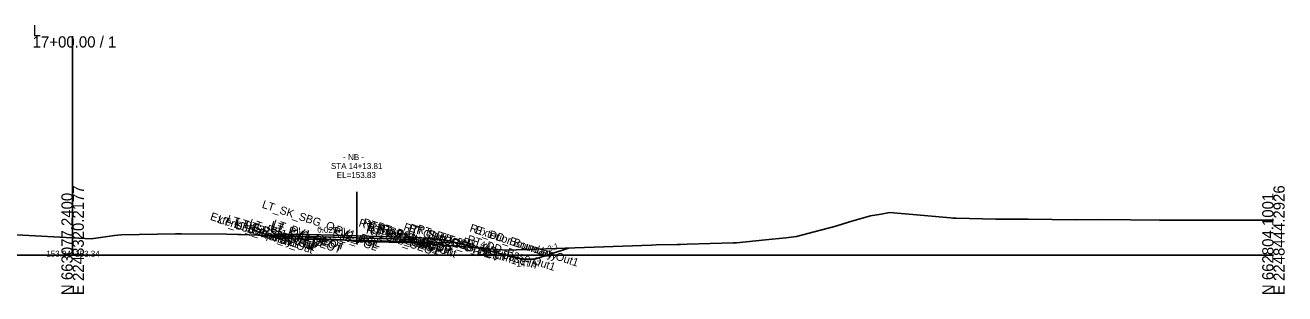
# Model space of a CAD drawing. Extents: x -26 to 2603, y -10 to 9566.
# Drawn here: x 288.1 to 602.8, y 6990.3 to 7057.6 of the extents above; entities that cross this region are included whole.
import ezdxf

# ---------------------------------------------------------------- set-up
doc = ezdxf.new("R2010")
doc.units = 0
for name, color, linetype in [('Exist Cross Section Cell', 7, 'Continuous'), ('Exist XS Center Line Elevation Label', 7, 'Continuous'), ('Exist XS Ground Line', 7, 'Continuous'), ('Prop CMT Ditch DDE', 7, 'Continuous'), ('Prop CMT Pvmt Course 1', 7, 'Continuous'), ('Prop CMT Pvmt Course 2', 7, 'Continuous'), ('Prop CMT Pvmt Surface', 7, 'Continuous'), ('Prop CMT Pvmt Surface Overlay', 7, 'Continuous'), ('Prop CMT Pvmt Surface Shoulder', 7, 'Continuous'), ('Prop CMT Shld Paved Course 1', 7, 'Continuous'), ('Prop CMT Shld Paved Course 2', 7, 'Continuous'), ('Prop CMT Slope Grass', 7, 'Continuous'), ('Prop CMT Subgrade Earthwork', 7, 'Continuous'), ('Prop XS Ditch Standard Text', 7, 'Continuous'), ('Prop XS SE Text', 7, 'Continuous'), ('Prop XS Side Slope Text', 7, 'Continuous'), ('Prop XS Vertical Lines Alignments', 7, 'Continuous'), ('Scratch_Level_1', 7, 'Continuous'), ('Scratch_Level_9', 7, 'Continuous')]:
    doc.layers.add(name, color=color, linetype=linetype)

msp = doc.modelspace()

# ---------------------------------------------------------------- linework, layer by layer
at = {"layer": 'Exist Cross Section Cell'}
for p, q in [((300, 7000), (300, 7054.78)), ((0, 7000), (300, 7000)), ((300, 7000), (600, 7000))]:
    msp.add_line(p, q, dxfattribs=at)
at = {"layer": 'Exist XS Ground Line'}
for p, q in [((490.67, 7007.28), (494.09, 7008.33)), ((494.09, 7008.33), (499.31, 7009.83)), ((499.31, 7009.83), (502.01, 7010.23)), ((502.01, 7010.23), (504.04, 7010.69)), ((504.04, 7010.69), (509.94, 7010.17)), ((509.94, 7010.17), (519.31, 7009.36)), ((519.31, 7009.36), (519.89, 7009.29)), ((519.89, 7009.29), (520.77, 7009.26)), ((520.77, 7009.26), (530.66, 7009.02)), ((530.66, 7009.02), (538.75, 7009)), ((538.75, 7009), (550.71, 7008.88)), ((550.71, 7008.88), (557.04, 7008.89)), ((557.04, 7008.89), (571.52, 7008.79)), ((571.52, 7008.79), (575.13, 7008.77)), ((575.13, 7008.77), (591.35, 7008.77)), ((591.35, 7008.77), (600, 7008.72)), ((286.01, 7005.1), (300, 7004.34)), ((310.44, 7004.88), (312.11, 7005.1)), ((312.11, 7005.1), (325.71, 7005.32)), ((325.71, 7005.32), (326.36, 7005.33)), ((326.36, 7005.33), (327.24, 7005.32)), ((327.24, 7005.32), (338.51, 7005.25)), ((338.51, 7005.25), (341.25, 7005.18)), ((341.25, 7005.18), (342.02, 7005.16)), ((342.02, 7005.16), (350.42, 7004.85)), ((480.87, 7004.63), (485.28, 7005.81)), ((485.28, 7005.81), (490.67, 7007.28)), ((300, 7004.34), (304.62, 7004.09)), ((304.62, 7004.09), (310.44, 7004.88)), ((350.42, 7004.85), (354.74, 7004.67)), ((354.74, 7004.67), (355.7, 7004.63)), ((355.7, 7004.63), (358.11, 7004.55)), ((358.11, 7004.55), (360.74, 7004.27)), ((360.74, 7004.27), (362.9, 7004)), ((362.9, 7004), (365.87, 7003.95)), ((365.87, 7003.95), (368.24, 7003.77)), ((368.24, 7003.77), (370.14, 7003.49)), ((370.14, 7003.49), (372.25, 7003.42)), ((372.25, 7003.42), (382.45, 7003.15)), ((382.45, 7003.15), (387.22, 7003.04)), ((387.22, 7003.04), (388.6, 7002.94)), ((388.6, 7002.94), (392.59, 7002.51)), ((392.59, 7002.51), (404.15, 7001.59)), ((418.2, 7001.59), (430.3, 7001.98)), ((430.3, 7001.98), (444.59, 7002.51)), ((444.59, 7002.51), (445.76, 7002.56)), ((445.76, 7002.56), (451.02, 7002.63)), ((451.02, 7002.63), (451.86, 7002.66)), ((451.86, 7002.66), (453.53, 7002.74)), ((453.53, 7002.74), (465.01, 7003.09)), ((465.01, 7003.09), (465.85, 7003.12)), ((465.85, 7003.12), (473.09, 7003.82)), ((473.09, 7003.82), (478.2, 7004.3)), ((478.2, 7004.3), (480.87, 7004.63)), ((404.15, 7001.59), (408.43, 7001.23)), ((408.43, 7001.23), (410.92, 7001.34)), ((410.92, 7001.34), (418.2, 7001.59))]:
    msp.add_line(p, q, dxfattribs=at)
at = {"layer": 'Prop CMT Ditch DDE'}
msp.add_lwpolyline([(401.01, 7001.83), (401.02, 7001.83), (412.46, 6998.97), (415.46, 6998.97), (423.85, 7001.77)], dxfattribs=at)
at = {"layer": 'Prop CMT Pvmt Course 1'}
for points in [[(370.97, 7004.83), (358.97, 7005.13)], [(358.97, 7005.13), (358.97, 7004.63)], [(358.97, 7004.63), (370.97, 7004.33)], [(370.97, 7004.33), (370.97, 7004.83)], [(370.97, 7004.83), (382.97, 7004.53)], [(370.97, 7004.33), (370.97, 7004.83)], [(382.97, 7004.03), (370.97, 7004.33)], [(382.97, 7004.53), (382.97, 7004.03)]]:
    msp.add_lwpolyline(points, dxfattribs=at)
at = {"layer": 'Prop CMT Pvmt Course 2'}
for points in [[(370.97, 7004.33), (358.97, 7004.63)], [(358.97, 7004.63), (358.97, 7003.97)], [(358.97, 7003.97), (370.97, 7003.67)], [(370.97, 7003.67), (370.97, 7004.33)], [(370.97, 7003.67), (370.97, 7004.33)], [(370.97, 7004.33), (382.97, 7004.03)], [(382.97, 7003.37), (370.97, 7003.67)], [(382.97, 7004.03), (382.97, 7003.37)]]:
    msp.add_lwpolyline(points, dxfattribs=at)
at = {"layer": 'Prop CMT Pvmt Surface'}
for points in [[(370.97, 7004.83), (358.97, 7005.13)], [(370.97, 7004.83), (382.97, 7004.53)]]:
    msp.add_lwpolyline(points, dxfattribs=at)
at = {"layer": 'Prop CMT Pvmt Surface Overlay'}
for points in [[(370.97, 7004.83), (358.97, 7005.13)], [(370.97, 7004.83), (382.97, 7004.53)]]:
    msp.add_lwpolyline(points, dxfattribs=at)
at = {"layer": 'Prop CMT Pvmt Surface Shoulder'}
for points in [[(358.97, 7005.13), (352.97, 7005.29)], [(382.97, 7004.53), (384.97, 7004.48)]]:
    msp.add_lwpolyline(points, dxfattribs=at)
at = {"layer": 'Prop CMT Shld Paved Course 1'}
for points in [[(358.97, 7005.13), (352.97, 7005.29), (352.48, 7004.8)], [(358.97, 7004.63), (358.97, 7005.13)], [(352.48, 7004.8), (358.97, 7004.63)], [(382.97, 7004.53), (384.97, 7004.48), (385.48, 7003.97)], [(382.97, 7004.03), (382.97, 7004.53)], [(385.48, 7003.97), (382.97, 7004.03)]]:
    msp.add_lwpolyline(points, dxfattribs=at)
at = {"layer": 'Prop CMT Shld Paved Course 2'}
for points in [[(358.97, 7004.63), (352.48, 7004.8), (351.98, 7004.81), (351.33, 7004.16)], [(351.33, 7004.16), (358.97, 7003.97)], [(358.97, 7003.97), (358.97, 7004.63)], [(382.97, 7004.03), (385.48, 7003.97), (385.98, 7003.96), (386.67, 7003.28)], [(382.97, 7003.37), (382.97, 7004.03)], [(386.67, 7003.28), (382.97, 7003.37)]]:
    msp.add_lwpolyline(points, dxfattribs=at)
at = {"layer": 'Prop CMT Slope Grass'}
for points in [[(350.96, 7005.21), (349.6, 7004.87)], [(352.97, 7005.29), (350.96, 7005.21)], [(384.97, 7004.48), (392.97, 7003.84)], [(392.97, 7003.84), (401.01, 7001.83)]]:
    msp.add_lwpolyline(points, dxfattribs=at)
at = {"layer": 'Prop CMT Subgrade Earthwork'}
msp.add_line((351.33, 7004.16), (349.6, 7004.87), dxfattribs=at)
for points in [[(358.97, 7003.97), (351.33, 7004.16)], [(351.33, 7004.16), (396.2, 7003.04)], [(370.97, 7003.67), (358.97, 7003.97)], [(370.97, 7003.67), (382.97, 7003.37)], [(382.97, 7003.37), (386.67, 7003.28)], [(386.67, 7003.28), (396.2, 7003.04)]]:
    msp.add_lwpolyline(points, dxfattribs=at)
at = {"layer": 'Prop XS Vertical Lines Alignments'}
msp.add_line((370.97, 7015.83), (370.97, 7002.83), dxfattribs=at)

# ---------------------------------------------------------------- texts
at = {"layer": 'Exist Cross Section Cell'}
for s, p in [('L', (290, 7054.78)), ('17+00.00 / 1', (290, 7051.98))]:
    msp.add_text(s, height=2.8, dxfattribs=at).set_placement(p)
for s, p in [('N 663077.2400', (300, 6990)), ('E 2248320.2177', (302.8, 6990)), ('N 662804.1001', (600, 6990)), ('E 2248444.2926', (602.8, 6990))]:
    msp.add_text(s, height=2.8, rotation=90, dxfattribs=at).set_placement(p)
at = {"layer": 'Exist XS Center Line Elevation Label'}
for p in [(293.42, 6999.59), (300.63, 6999.59)]:
    msp.add_text('153.34', height=1.5, dxfattribs=at).set_placement(p)
at = {"layer": 'Prop XS Ditch Standard Text'}
msp.add_text('147.97', height=1.5, dxfattribs=at).set_placement((410.88, 6997.15))
at = {"layer": 'Prop XS SE Text'}
for p in [(361.1, 7005.64), (374.3, 7005.18)]:
    msp.add_text('0.025', height=1.5, rotation=358.5434, dxfattribs=at).set_placement(p)
at = {"layer": 'Prop XS Side Slope Text'}
for s, rotation, p in [('4:1', 346.0018, (401.78, 7002.17)), ('3:1', 18.4232, (418.97, 7000.78))]:
    msp.add_text(s, height=1.5, rotation=rotation, dxfattribs=at).set_placement(p)
at = {"layer": 'Prop XS Vertical Lines Alignments'}
for s, p in [('- NB -', (367.58, 7023.81)), ('STA 14+13.81', (364.52, 7021.56))]:
    msp.add_text(s, height=1.5, dxfattribs=at).set_placement(p)
at = {"layer": 'Scratch_Level_1'}
msp.add_text('EL=153.83', height=1.5, dxfattribs=at).set_placement((366, 7019.31))
at = {"layer": 'Scratch_Level_9'}
for s, p in [('LT_SK_SBG_O', (347.15, 7011.9)), ('Exterior Boundary', (334.22, 7008.88)), ('LT_Sub_Trench_Out', (336.02, 7008.15)), ('LT_PS2_Shelf_Out', (338.36, 7008.24)), ('LT_Slope_Fill', (340.28, 7006.89)), ('LT_GS_OS_CTL', (340.55, 7007.59)), ('LT_PS2_OEOP', (342.9, 7006.9)), ('LT_PS1_OEOP', (343.92, 7007.21)), ('LT_PV2_OEOT', (349.32, 7006.76)), ('LT_PV1_OEOT', (349.86, 7007.08)), ('RT_Sub_Trench_Out', (371.31, 7007.28)), ('RT_PS2_Shelf_Out', (372.31, 7007.4)), ('RT_PV1_OEOT', (373.82, 7006.49)), ('RT_PS1_OEOP', (375.88, 7006.42)), ('LT_Sub_OEOT', (349.23, 7006.12)), ('Sub_PGL', (364.78, 7004.65)), ('PV2_PGL', (364.87, 7005.29)), ('PV1_PGL', (365.41, 7005.61)), ('RT_Sub_OEOT', (373.19, 7005.53)), ('RT_PV2_OEOT', (373.28, 7006.17)), ('RT_PS2_OEOP', (375.85, 7006.09)), ('RT_GS_OS_CTL', (382.52, 7006.23)), ('RT_Sub_OSS_DLT', (383.88, 7006.04)), ('LT_Sub_OSS_DLT', (383.92, 7006.02)), ('RT_DD_Boundary In1', (385.81, 7005.79)), ('RT_Slope_Fill', (391.65, 7003.86)), ('RT_DD_Base Out1', (398.37, 7003.22)), ('RT_DD_Boundary Out1', (399.04, 7005.97)), ('Exterior Boundary', (400.42, 7005.51)), ('RT_DD_Base In', (397.22, 7002.61))]:
    msp.add_text(s, height=2, rotation=341.787, dxfattribs=at).set_placement(p)

doc.saveas('drawing.dxf')
